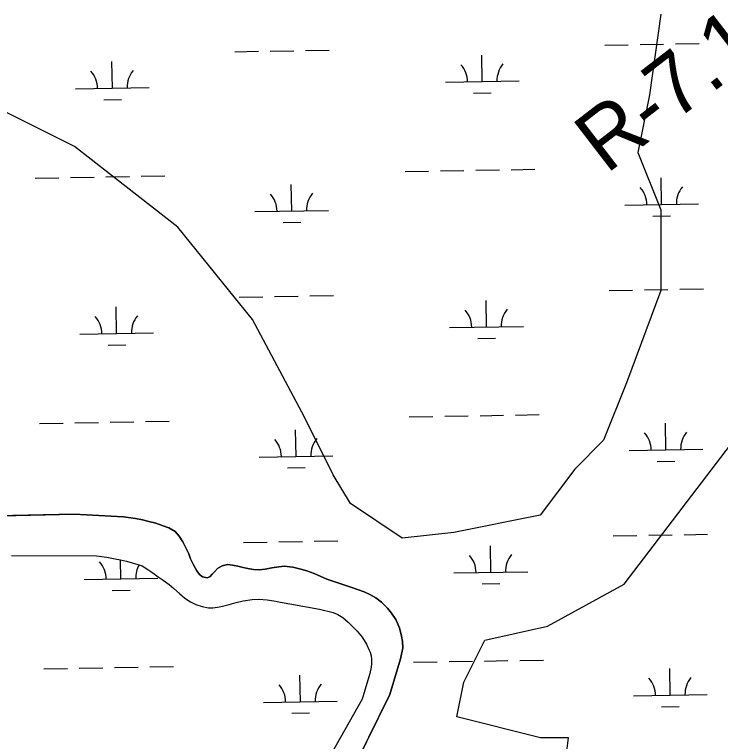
# Model space of a CAD drawing. Extents: x 3903937 to 3942190, y 260677 to 286651.
# Drawn here: x 3924784 to 3925742, y 273792 to 274777 of the extents above; entities that cross this region are included whole.
import ezdxf

# ---------------------------------------------------------------- set-up
doc = ezdxf.new("R2010")
doc.units = 0
for name, color, linetype in [('V-RIVR-RANG-IDEN', 7, 'Continuous'), ('V-SITE-VEGE', 7, 'Continuous'), ('V-TOPO-SHOR', 7, 'Continuous'), ('V-WETL-SWMP', 7, 'Continuous')]:
    doc.layers.add(name, color=color, linetype=linetype)

msp = doc.modelspace()

# ---------------------------------------------------------------- linework, layer by layer
at = {"layer": 'V-SITE-VEGE'}
for p, q in [((3925661.02, 274777.82), (3925645.41, 274668.52)), ((3924865.11, 274598.26), (3924662.23, 274699.75)), ((3925645.41, 274668.52), (3925629.8, 274590.45)), ((3925005.57, 274488.96), (3924865.11, 274598.26)), ((3925629.8, 274590.45), (3925661.02, 274512.39)), ((3925661.02, 274512.39), (3925661.02, 274403.09)), ((3925107, 274364.05), (3925005.57, 274488.96)), ((3925661.02, 274403.09), (3925614.2, 274278.18)), ((3925177.23, 274231.34), (3925107, 274364.05)), ((3925614.2, 274278.18), (3925582.99, 274200.11)), ((3925216.25, 274153.27), (3925177.23, 274231.34)), ((3925582.99, 274200.11), (3925543.97, 274161.08)), ((3925543.97, 274161.08), (3925497.15, 274098.62)), ((3925239.66, 274114.23), (3925216.25, 274153.27)), ((3925309.88, 274067.39), (3925239.66, 274114.23)), ((3925497.15, 274098.62), (3925380.11, 274075.2)), ((3925380.11, 274075.2), (3925309.88, 274067.39))]:
    msp.add_line(p, q, dxfattribs=at)
msp.add_lwpolyline([(3925762.46, 274203.56), (3925790.83, 274288.72), (3925838.11, 274354.95), (3925894.86, 274326.57), (3925932.69, 274260.33), (3925913.77, 274175.17), (3925942.15, 274118.4), (3925970.52, 274061.63), (3925998.89, 273948.09), (3925979.97, 273862.93), (3925923.23, 273815.62), (3925771.92, 273711.54), (3925658.43, 273654.77), (3925554.4, 273664.23), (3925526.03, 273721), (3925535.48, 273796.7), (3925497.66, 273796.7), (3925384.17, 273825.08), (3925393.62, 273872.39), (3925422, 273929.16), (3925507.11, 273948.09), (3925611.14, 274004.86)], close=True, dxfattribs=at)
at = {"layer": 'V-TOPO-SHOR'}
for points in [[(3924726.61, 274096.9), (3924864.96, 274100.02), (3924931.66, 274096.5), (3924947.93, 274093.91), (3924957.46, 274092.18), (3924966.02, 274090.13), (3924975.44, 274087.65), (3924984.32, 274084.64), (3924993.31, 274081.31), (3925001.66, 274076.59), (3925007.11, 274070.16), (3925012.45, 274062.65), (3925016.08, 274055.26), (3925020.24, 274046.05), (3925022.8, 274039.4), (3925026.86, 274031.47), (3925031.35, 274023.12), (3925034.87, 274018.29), (3925039.15, 274014.97), (3925045.46, 274013.78), (3925048.79, 274015.17), (3925052.22, 274018.8), (3925055.11, 274022.01), (3925059.19, 274026.18), (3925065.51, 274029.92), (3925072.9, 274031.84), (3925079.65, 274030.76), (3925087.03, 274029.36), (3925094.31, 274027.53), (3925100.63, 274026.23), (3925108.01, 274024.93), (3925115.72, 274024.71), (3925124.07, 274025.55), (3925133.18, 274027.36), (3925142.5, 274028.74), (3925149.67, 274029.27), (3925161.34, 274028.18), (3925172.47, 274025.59), (3925180.71, 274023.12), (3925190.34, 274019.57), (3925207.57, 274011.84), (3925241.71, 274000.44), (3925258.3, 273994.63), (3925266.11, 273991.2), (3925274.24, 273986.37), (3925281.83, 273980.47), (3925289.75, 273972.53), (3925295.52, 273965.99), (3925301.4, 273957.31), (3925306.3, 273946.06), (3925309.18, 273934.71), (3925310.35, 273927.21), (3925310.55, 273918.86), (3925310.01, 273914.04), (3925307.42, 273903.98), (3925293.33, 273855.49), (3925229.87, 273727.2)], [(3924779.96, 274044.01), (3924895.32, 274043.63), (3924909.34, 274041.68), (3924920.58, 274039.44), (3924927.8, 274038), (3924935.96, 274036.2), (3924943.54, 274034.19), (3924951.34, 274031.81), (3924956.99, 274029.8), (3924964.71, 274025), (3924968.71, 274022.34), (3924973.22, 274019.12), (3924978.58, 274015.24), (3924985.37, 274010.44), (3924993.52, 274004.42), (3924999.88, 273999.04), (3925007.74, 273992.3), (3925015.18, 273986.07), (3925022.83, 273980.98), (3925030.05, 273977.39), (3925038.7, 273974.58), (3925047.15, 273972.78), (3925053.16, 273972.92), (3925059.39, 273973.84), (3925066.26, 273975.33), (3925074.99, 273977.68), (3925084.66, 273980.39), (3925094.32, 273982.52), (3925106.2, 273984.51), (3925115.58, 273984.78), (3925126.67, 273983.83), (3925135.9, 273982.53), (3925144.91, 273980.87), (3925157.5, 273978.64), (3925197.5, 273971.21)], [(3925197.5, 273971.21), (3925216.24, 273966.74), (3925222.46, 273964.09), (3925229.54, 273959.78), (3925236.62, 273953.47), (3925242.98, 273947.24), (3925248.98, 273941.22), (3925255.62, 273933.41), (3925261.62, 273923.96), (3925264.54, 273916.58)], [(3925264.54, 273916.58), (3925266.25, 273912.79), (3925267.75, 273907.77), (3925268.25, 273903.55), (3925268.31, 273896.9), (3925267.66, 273892.46), (3925266.07, 273884.16), (3925255.5, 273848.97), (3925208.58, 273766.16)]]:
    msp.add_lwpolyline(points, dxfattribs=at)
at = {"layer": 'V-WETL-SWMP'}
for p, q in [((3925584.67, 274735.72), (3925616.67, 274736.28)), ((3925632.66, 274736.56), (3925664.66, 274737.12)), ((3925680.66, 274737.41), (3925712.65, 274737.97)), ((3925082.84, 274726.88), (3925114.84, 274727.45)), ((3925130.83, 274727.73), (3925162.83, 274728.29)), ((3925178.83, 274728.57), (3925210.82, 274729.14)), ((3925418.45, 274686.35), (3925417.82, 274722.35)), ((3924916.62, 274677.52), (3924915.99, 274713.51)), ((3925368.46, 274685.47), (3925468.44, 274687.23)), ((3924866.63, 274676.64), (3924966.61, 274678.4)), ((3924904.89, 274661.88), (3924928.89, 274662.3)), ((3925406.72, 274670.71), (3925430.72, 274671.14)), ((3925313.74, 274564.42), (3925345.73, 274564.98)), ((3925361.73, 274565.27), (3925393.72, 274565.83)), ((3925409.72, 274566.11), (3925441.72, 274566.67)), ((3925457.71, 274566.96), (3925489.71, 274567.52)), ((3924811.91, 274555.59), (3924843.9, 274556.15)), ((3924859.9, 274556.43), (3924891.89, 274557)), ((3924907.89, 274557.28), (3924939.89, 274557.84)), ((3924955.88, 274558.12), (3924987.88, 274558.69)), ((3925661.89, 274519.8), (3925661.26, 274555.79)), ((3925160.06, 274510.97), (3925159.43, 274546.96)), ((3925611.9, 274518.92), (3925711.88, 274520.68)), ((3925110.07, 274510.09), (3925210.05, 274511.85)), ((3925650.16, 274504.16), (3925674.16, 274504.58)), ((3925148.33, 274495.33), (3925172.33, 274495.75)), ((3925686.51, 274404.78), (3925718.51, 274405.35)), ((3925136.69, 274395.1), (3925168.68, 274395.67)), ((3925184.68, 274395.95), (3925216.68, 274396.51)), ((3925590.53, 274403.09), (3925622.52, 274403.66)), ((3925638.52, 274403.94), (3925670.51, 274404.5)), ((3925088.7, 274394.26), (3925120.69, 274394.82)), ((3925424.3, 274353.73), (3925423.67, 274389.72)), ((3924922.47, 274344.9), (3924921.84, 274380.89)), ((3925374.31, 274352.85), (3925474.3, 274354.61)), ((3924872.48, 274344.02), (3924972.47, 274345.78)), ((3925412.58, 274338.09), (3925436.57, 274338.51)), ((3924910.75, 274329.26), (3924934.74, 274329.68)), ((3925319.59, 274231.8), (3925351.59, 274232.36)), ((3925367.58, 274232.64), (3925399.58, 274233.21)), ((3925415.58, 274233.49), (3925447.57, 274234.05)), ((3925463.57, 274234.33), (3925495.56, 274234.89)), ((3924817.76, 274222.96), (3924849.76, 274223.53)), ((3924865.75, 274223.81), (3924897.75, 274224.37)), ((3924913.75, 274224.65), (3924945.74, 274225.22)), ((3924961.74, 274225.5), (3924993.73, 274226.06)), ((3925667.75, 274187.18), (3925667.11, 274223.17)), ((3925165.92, 274178.34), (3925165.28, 274214.34)), ((3925115.92, 274177.46), (3925215.91, 274179.22)), ((3925617.75, 274186.3), (3925717.74, 274188.06)), ((3925656.02, 274171.54), (3925680.02, 274171.96)), ((3925154.19, 274162.7), (3925178.19, 274163.13)), ((3924864.96, 274100.02), (3924726.61, 274096.9)), ((3924931.66, 274096.5), (3924864.96, 274100.02)), ((3924947.93, 274093.9), (3924931.66, 274096.5)), ((3924957.46, 274092.18), (3924947.93, 274093.9)), ((3924966.02, 274090.13), (3924957.46, 274092.18)), ((3924975.44, 274087.65), (3924966.02, 274090.13)), ((3924984.32, 274084.64), (3924975.44, 274087.65)), ((3924993.31, 274081.31), (3924984.32, 274084.64)), ((3925001.66, 274076.59), (3924993.31, 274081.31)), ((3925007.11, 274070.16), (3925001.66, 274076.59)), ((3925012.45, 274062.65), (3925007.11, 274070.16)), ((3925596.38, 274070.47), (3925628.38, 274071.03)), ((3925644.37, 274071.31), (3925676.37, 274071.88)), ((3925692.37, 274072.16), (3925724.36, 274072.72)), ((3925016.08, 274055.26), (3925012.45, 274062.65)), ((3925094.55, 274061.64), (3925126.55, 274062.2)), ((3925142.54, 274062.48), (3925174.54, 274063.04)), ((3925190.54, 274063.33), (3925222.53, 274063.89)), ((3925020.24, 274046.05), (3925016.08, 274055.26)), ((3925430.16, 274021.11), (3925429.53, 274057.1)), ((3925022.8, 274039.4), (3925020.24, 274046.05)), ((3924928.33, 274012.27), (3924927.88, 274037.99)), ((3925026.86, 274031.47), (3925022.8, 274039.4)), ((3925031.35, 274023.12), (3925026.86, 274031.47)), ((3925072.9, 274031.84), (3925065.51, 274029.92)), ((3925079.65, 274030.76), (3925072.9, 274031.84)), ((3925087.03, 274029.35), (3925079.65, 274030.76)), ((3925034.87, 274018.29), (3925031.35, 274023.12)), ((3925055.11, 274022.01), (3925052.22, 274018.8)), ((3925059.19, 274026.18), (3925055.11, 274022.01)), ((3925065.51, 274029.92), (3925059.19, 274026.18)), ((3925094.31, 274027.52), (3925087.03, 274029.35)), ((3925100.62, 274026.23), (3925094.31, 274027.52)), ((3925108.01, 274024.93), (3925100.62, 274026.23)), ((3925115.72, 274024.71), (3925108.01, 274024.93)), ((3925124.07, 274025.55), (3925115.72, 274024.71)), ((3925133.18, 274027.36), (3925124.07, 274025.55)), ((3925142.5, 274028.74), (3925133.18, 274027.36)), ((3925149.67, 274029.26), (3925142.5, 274028.74)), ((3925161.34, 274028.18), (3925149.67, 274029.26)), ((3925172.47, 274025.59), (3925161.34, 274028.18)), ((3925180.71, 274023.12), (3925172.47, 274025.59)), ((3925190.34, 274019.57), (3925180.71, 274023.12)), ((3925380.17, 274020.23), (3925480.15, 274021.99)), ((3924878.34, 274011.39), (3924978.32, 274013.15)), ((3925039.15, 274014.97), (3925034.87, 274018.29)), ((3925045.46, 274013.78), (3925039.15, 274014.97)), ((3925048.79, 274015.17), (3925045.46, 274013.78)), ((3925052.22, 274018.8), (3925048.79, 274015.17)), ((3925207.57, 274011.84), (3925190.34, 274019.57)), ((3925241.71, 274000.44), (3925207.57, 274011.84)), ((3925418.43, 274005.47), (3925442.43, 274005.89)), ((3924916.6, 273996.63), (3924940.6, 273997.06)), ((3925258.3, 273994.63), (3925241.71, 274000.44)), ((3925266.11, 273991.2), (3925258.3, 273994.63)), ((3925274.24, 273986.37), (3925266.11, 273991.2)), ((3925281.83, 273980.47), (3925274.24, 273986.37)), ((3925289.75, 273972.53), (3925281.83, 273980.47)), ((3925295.52, 273965.99), (3925289.75, 273972.53)), ((3925301.4, 273957.31), (3925295.52, 273965.99)), ((3925306.31, 273946.06), (3925301.4, 273957.31)), ((3925309.18, 273934.71), (3925306.31, 273946.06)), ((3925310.35, 273927.21), (3925309.18, 273934.71)), ((3925310.55, 273918.86), (3925310.35, 273927.21)), ((3925307.42, 273903.98), (3925310.01, 273914.04)), ((3925310.01, 273914.04), (3925310.55, 273918.86)), ((3925293.33, 273855.49), (3925307.42, 273903.98)), ((3924967.59, 273892.88), (3924999.59, 273893.44)), ((3925325.45, 273899.17), (3925357.44, 273899.74)), ((3925373.44, 273900.02), (3925405.43, 273900.58)), ((3925421.43, 273900.86), (3925453.43, 273901.43)), ((3925469.42, 273901.71), (3925501.42, 273902.27)), ((3924823.61, 273890.34), (3924855.61, 273890.9)), ((3924871.61, 273891.19), (3924903.6, 273891.75)), ((3924919.6, 273892.03), (3924951.6, 273892.59)), ((3925673.6, 273854.55), (3925672.97, 273890.55)), ((3925171.77, 273845.72), (3925171.14, 273881.71)), ((3925229.86, 273727.21), (3925293.33, 273855.49)), ((3925623.61, 273853.67), (3925723.59, 273855.43)), ((3925121.78, 273844.84), (3925221.76, 273846.6)), ((3925661.87, 273838.91), (3925685.87, 273839.33)), ((3925160.04, 273830.08), (3925184.04, 273830.5))]:
    msp.add_line(p, q, dxfattribs=at)
msp.add_lwpolyline([(3924779.96, 274044.01), (3924895.32, 274043.63), (3924909.34, 274041.68), (3924920.58, 274039.44), (3924927.8, 274038), (3924935.96, 274036.2), (3924943.54, 274034.19), (3924951.34, 274031.81), (3924956.99, 274029.8), (3924964.71, 274025), (3924968.71, 274022.34), (3924973.22, 274019.12), (3924978.58, 274015.24), (3924985.37, 274010.44), (3924993.52, 274004.42), (3924999.88, 273999.04), (3925007.74, 273992.3), (3925015.18, 273986.07), (3925022.83, 273980.97), (3925030.05, 273977.39), (3925038.7, 273974.58), (3925047.15, 273972.78), (3925053.16, 273972.92), (3925059.39, 273973.84), (3925066.26, 273975.33), (3925074.99, 273977.68), (3925084.66, 273980.39), (3925094.32, 273982.52), (3925106.2, 273984.51), (3925115.58, 273984.78), (3925126.67, 273983.83), (3925135.9, 273982.53), (3925144.91, 273980.87), (3925157.5, 273978.64), (3925197.5, 273971.21), (3925216.24, 273966.74), (3925222.46, 273964.09), (3925229.54, 273959.78), (3925236.62, 273953.48), (3925242.98, 273947.24), (3925248.98, 273941.22), (3925255.62, 273933.41), (3925261.62, 273923.96), (3925264.54, 273916.58), (3925266.26, 273912.79), (3925267.75, 273907.78), (3925268.25, 273903.55), (3925268.31, 273896.9), (3925267.66, 273892.46), (3925266.07, 273884.16), (3925255.5, 273848.97), (3925208.58, 273766.17)], dxfattribs=at)
for centre, start, end in [((3924971.85, 274678.97), 140.23658, 181.78024), ((3925363.21, 274685.86), 0.23658, 41.78024), ((3925473.68, 274687.8), 140.23658, 181.78024), ((3924861.38, 274677.02), 0.23658, 41.78024), ((3925717.12, 274521.25), 140.23658, 181.78024), ((3925104.82, 274510.47), 0.23658, 41.78024), ((3925215.29, 274512.41), 140.23658, 181.78024), ((3925606.65, 274519.3), 0.23658, 41.78024), ((3925369.06, 274353.23), 0.23658, 41.78024), ((3925479.53, 274355.18), 140.23658, 181.78024), ((3924867.23, 274344.4), 0.23658, 41.78024), ((3924977.7, 274346.34), 140.23658, 181.78024), ((3925612.5, 274186.68), 0.23658, 41.78024), ((3925722.97, 274188.62), 140.23658, 181.78024), ((3925110.67, 274177.85), 0.23658, 41.78024), ((3925221.14, 274179.79), 140.23658, 181.78024), ((3925374.92, 274020.61), 0.23658, 41.78024), ((3925485.39, 274022.55), 140.23658, 181.78024), ((3924873.09, 274011.78), 0.23658, 41.78024), ((3924983.56, 274013.72), 150.20659, 181.78024), ((3925618.36, 273854.05), 0.23658, 41.78024), ((3925728.83, 273856), 140.23658, 181.78024), ((3925116.53, 273845.22), 0.23658, 41.78024), ((3925227, 273847.17), 140.23658, 181.78024)]:
    msp.add_arc(centre, 35.25, start, end, dxfattribs=at)

# ---------------------------------------------------------------- texts
at = {"layer": 'V-RIVR-RANG-IDEN'}
msp.add_text('R-7.1', height=83, rotation=37.59118, dxfattribs=at).set_placement((3925586.74, 274560.12))

doc.saveas('drawing.dxf')
